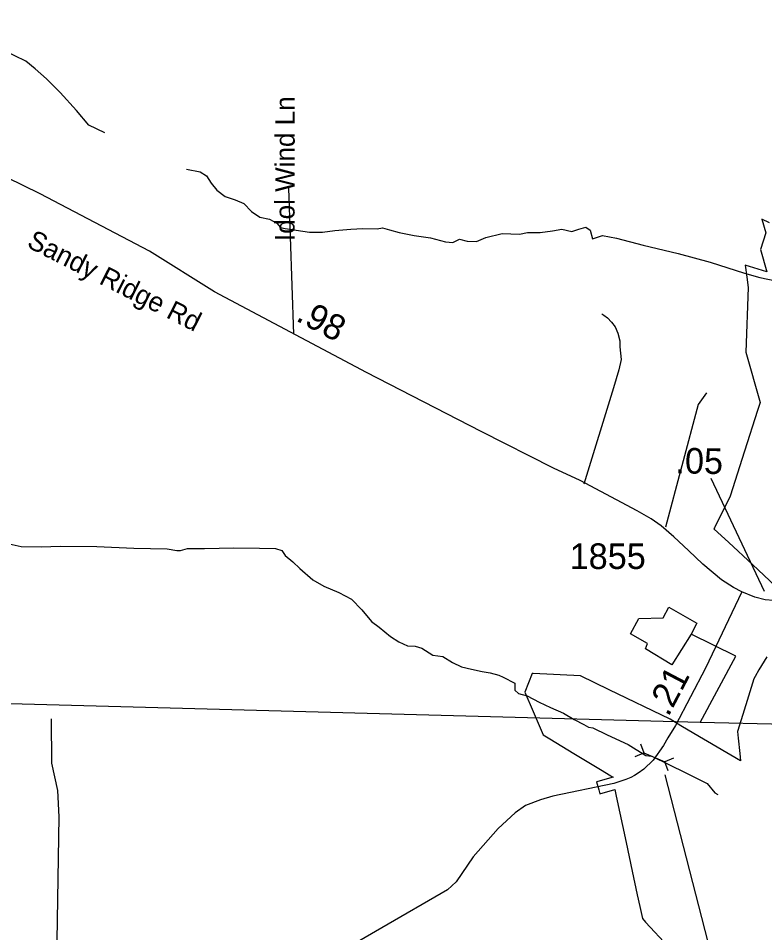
# Model space of a CAD drawing. Extents: x 1662474 to 1856135, y 779280 to 917889.
# Drawn here: x 1694127 to 1697773, y 839326 to 843789 of the extents above; entities that cross this region are included whole.
import ezdxf

# ---------------------------------------------------------------- set-up
doc = ezdxf.new("R2010")
doc.units = 0
for name, color, linetype in [('Exist Boundary Political City Limit New', 7, 'Continuous'), ('Exist Hydrographic Creek Single Shore', 7, 'Continuous'), ('Exist Road Non-System Type 51', 7, 'Continuous'), ('Exist Road Non-System Type 51 Label', 7, 'Continuous'), ('Exist Road Secondary Mileage Hundredths English Label', 7, 'Continuous'), ('Exist Road Secondary Mileage Tenths English Label', 7, 'Continuous'), ('Exist Road Secondary Structure Pipe CELL', 7, 'Continuous'), ('Exist Road Secondary Structure Pipe Number Label', 7, 'Continuous'), ('Exist Road Secondary Type 51 Attributed', 7, 'Continuous'), ('Exist Road Secondary Type 51 Label', 7, 'Continuous'), ('Exist Road Secondary Type 51 Number Label', 7, 'Continuous'), ('Exist Utilities Electrical Transmission Line', 7, 'Continuous'), ('Map Preparation Boundary City Limit Buffer Line', 7, 'Continuous')]:
    doc.layers.add(name, color=color, linetype=linetype)

msp = doc.modelspace()

# ---------------------------------------------------------------- linework, layer by layer
at = {"layer": 'Exist Boundary Political City Limit New'}
for points in [[(1697797.1, 842790.2), (1697759.9, 842808.9), (1697778.6, 842742.1), (1697752.8, 842661.1), (1697783.4, 842551.6), (1697677.9, 842584.1), (1697685.9, 842525.6), (1697692.6, 842475.4), (1697681.2, 842158.8), (1697750.5, 841914.4), (1697738, 841874.9), (1697674.9, 841675.7), (1697605.2, 841456.2), (1697527.9, 841302.1), (1697525.2, 841296.9), (1697597.6, 841229.8), (1697712.9, 841122.9), (1697826.6, 841017.4)], [(1697783.6, 840673.1), (1697745.4, 840608.4), (1697727.1, 840576.4), (1697720.4, 840564.9), (1697694.4, 840480.8), (1697666.4, 840390.5), (1697640.9, 840308.2), (1697644, 840275.1), (1697651.2, 840200.8), (1697654.8, 840164.2), (1697426.5, 840298.2), (1697363.4, 840335.2), (1697311.6, 840367.6), (1697014, 840512), (1696873.1, 840580.4), (1696641.9, 840591.4), (1696637.6, 840591.6), (1696601.8, 840499.2), (1696642.1, 840405.1), (1696690.5, 840292.2), (1696723.8, 840272.1), (1696840.6, 840201.3), (1696913.4, 840157.2), (1696971.1, 840122.3), (1697020.9, 840092.2), (1697027, 840088.4), (1697032.5, 840085.1)], [(1697032.5, 840085.1), (1696981.5, 840070.5), (1696954, 840062.6), (1696951, 840061.8), (1696962.5, 840023.4), (1696968.5, 840003.2), (1697041.1, 840024.7), (1697047, 839992.9), (1697095.8, 839766.4), (1697126, 839626.1), (1697150.8, 839510.9), (1697163, 839453.9), (1697175.9, 839394.4), (1697191, 839377.4), (1697303.5, 839257.3)]]:
    msp.add_lwpolyline(points, dxfattribs=at)
at = {"layer": 'Exist Hydrographic Creek Single Shore'}
for points in [[(1694549.1, 843229.5), (1694470.9, 843267.1), (1694411.2, 843340), (1694330.8, 843427.1), (1694265.1, 843494.1), (1694209.8, 843543.4), (1694164.4, 843580.4), (1694056.8, 843631.9), (1694004.8, 843658.1), (1693935, 843671.2), (1693848.6, 843674.6), (1693766.5, 843694.1), (1693662, 843700.4), (1693561.2, 843692.8), (1693510.2, 843680.9), (1693485.6, 843702.4), (1693391.4, 843789.3)], [(1694948.8, 843053.4), (1695015.8, 843040.3), (1695047, 843021.1), (1695069, 842984.7), (1695096.2, 842950.6), (1695137.5, 842919.1), (1695185.8, 842902.5), (1695229.4, 842884.7), (1695266.6, 842845.8), (1695307, 842818.2), (1695353.8, 842809.4), (1695390, 842789.9), (1695407.5, 842767.9), (1695429.9, 842763.4), (1695549.2, 842745.6), (1695613.4, 842745.1), (1695672.6, 842753.9), (1695732, 842758.2), (1695750.9, 842760.2), (1695809.6, 842763.1), (1695880.5, 842761.8), (1695906.2, 842767.1), (1695940.4, 842757.1), (1695987, 842742.9), (1696061.6, 842729.1), (1696141.4, 842718.2), (1696214.4, 842698.1), (1696249.5, 842695.4), (1696282.9, 842711.2), (1696319, 842701.8), (1696365.2, 842699.1), (1696411.4, 842718.6), (1696491, 842738.8), (1696574.9, 842735.6), (1696613.8, 842744.5), (1696676.2, 842744), (1696736.6, 842752.4), (1696783, 842760.5), (1696831.6, 842749.2), (1696865.5, 842759.2), (1696898.8, 842769.2), (1696920.6, 842754.8), (1696932.1, 842712.8), (1696981, 842729.1), (1697048.9, 842716.4), (1697179.6, 842681.8), (1697350.2, 842640.9), (1697506.9, 842598.1), (1697674.6, 842545.3), (1697749.9, 842523.8), (1697835.2, 842506.2)], [(1694053.2, 841229.9), (1694141.2, 841211), (1694238.1, 841208.7), (1694332.5, 841212.1), (1694511, 841210.8), (1694691.4, 841202.1), (1694854.6, 841199.8), (1694901.2, 841191.6), (1694920.1, 841191.1), (1694954, 841201.6), (1695000, 841201.1), (1695037.2, 841200.5), (1695179.5, 841204.8), (1695305.8, 841202.4), (1695383.6, 841200.8), (1695414.4, 841191.6), (1695430.9, 841166.4), (1695468.8, 841135.4), (1695501.8, 841104.2), (1695565.9, 841048.3), (1695619.9, 841016.6), (1695692.4, 840985.8), (1695755, 840954.1), (1695805.8, 840901.1), (1695851.9, 840845.7), (1695890, 840817.9), (1695944.8, 840771.9), (1695986.5, 840745.2), (1696027.8, 840726.8), (1696066, 840724.7), (1696099.1, 840714.2), (1696152.1, 840680.4), (1696201.2, 840673.5), (1696247.4, 840644.1), (1696292.2, 840623.4), (1696341.6, 840612.1), (1696392.5, 840600.6), (1696432.1, 840593.8), (1696474.1, 840582.7), (1696496, 840572.8), (1696552.4, 840543.9), (1696552.9, 840510.2), (1696570, 840492.7), (1696613.2, 840482.2), (1696671.5, 840450.9), (1696726.4, 840425.2), (1696790.6, 840397.4), (1696842.9, 840367.2), (1696889.4, 840342.1), (1696912.8, 840329.4), (1696933.8, 840326.1), (1697003.2, 840291.9), (1697107.1, 840244.4), (1697193.2, 840190.1), (1697222.4, 840187.2), (1697388, 840106.9), (1697492.2, 840054.4), (1697529.2, 840009), (1697543.9, 840000.1)]]:
    msp.add_lwpolyline(points, dxfattribs=at)
at = {"layer": 'Exist Road Non-System Type 51'}
msp.add_line((1695472.8, 842247.4), (1695447.9, 842959.8), dxfattribs=at)
for points in [[(1696976.9, 842346.7), (1696986.9, 842340.9), (1697005, 842327.2), (1697025.2, 842306.8), (1697042.6, 842283.1), (1697056.1, 842252.4), (1697066.1, 842215.7), (1697066.4, 842185.5), (1697072.5, 842123.9), (1697059.9, 842072.9), (1697034.1, 841984.7), (1696889.8, 841515.7)], [(1697488.5, 841961.9), (1697448.9, 841903.6), (1697288.5, 841305.8)], [(1694288.2, 840370.4), (1694289.9, 840153.8), (1694317.9, 840019.2), (1694325.2, 839891.4), (1694315.6, 839288.2), (1694329.8, 838810.2), (1694332.1, 838562.8), (1694336.6, 838412.4)]]:
    msp.add_lwpolyline(points, dxfattribs=at)
at = {"layer": 'Exist Road Secondary Mileage Tenths English Label'}
msp.add_line((1697772.9, 840991.5), (1697511.4, 841543.1), dxfattribs=at)
at = {"layer": 'Exist Road Secondary Structure Pipe CELL'}
for p, q in [((1697139.9, 840185.7), (1697183, 840204.2)), ((1697166.9, 840248.2), (1697183, 840204.2)), ((1697183, 840204.2), (1697285.5, 840160)), ((1697328.5, 840178.5), (1697285.5, 840160)), ((1697301.6, 840116), (1697285.5, 840160))]:
    msp.add_line(p, q, dxfattribs=at)
at = {"layer": 'Exist Road Secondary Structure Pipe Number Label'}
msp.add_line((1697285.7, 840096.9), (1697814.5, 838042.6), dxfattribs=at)
at = {"layer": 'Exist Road Secondary Type 51 Attributed'}
for points in [[(1697662, 840989.5), (1697620.8, 841010.1), (1697562.4, 841049), (1697470.8, 841124.6), (1697401, 841192.1), (1697328.9, 841258.5), (1697267, 841312.3), (1697219, 841346.7), (1697150.3, 841384.5), (1696872.1, 841532.5), (1696741.6, 841592.8), (1696388.9, 841772.6), (1695827.4, 842059.9), (1695085.5, 842454.9), (1694767.3, 842653), (1694233.2, 842932.3), (1693740.9, 843172.7), (1693379.1, 843374.2), (1693151.3, 843525.3)], [(1697662, 840989.5), (1697484.5, 840617.2), (1697337.7, 840337.8), (1697300.5, 840277.5), (1697279, 840239.8), (1697227.7, 840167.4), (1697183.3, 840124.9), (1697155.9, 840105), (1697138, 840092.7), (1697119.1, 840083.3), (1697095.5, 840072.9)], [(1697991.4, 840957.4), (1697962.5, 840954), (1697899, 840944.8), (1697816.3, 840947.1), (1697775.4, 840950.6), (1697725.3, 840964.3), (1697662, 840989.5)], [(1697095.5, 840072.9), (1697036, 840054), (1696738.7, 839992.6), (1696678.3, 839975.1), (1696604.6, 839946.8), (1696553.7, 839910.9), (1696470.6, 839835.3), (1696349.2, 839696.9), (1696265.3, 839573.7), (1696223.4, 839534.4), (1695903.5, 839348.9), (1695192.9, 838937.5), (1694576, 838564.2), (1694339.4, 838423.4), (1694221.1, 838325.9), (1694099.1, 838209.5), (1693911.4, 838007.3)]]:
    msp.add_lwpolyline(points, dxfattribs=at)
at = {"layer": 'Exist Utilities Electrical Transmission Line'}
for p, q in [((1697457.4, 840352.2), (1692050.9, 840498.4)), ((1704475.7, 840197.4), (1697457.4, 840352.2))]:
    msp.add_line(p, q, dxfattribs=at)
for points in [[(1697414, 840782.9), (1697320.4, 840633.7), (1697191.1, 840711.2), (1697201.4, 840737.2), (1697117.9, 840784.1), (1697158.8, 840859.7), (1697276.8, 840862.3), (1697305.4, 840914.2), (1697442.5, 840836.6), (1697414, 840782.9)], [(1697457.4, 840352.2), (1697632.8, 840676.4), (1697414, 840782.9)]]:
    msp.add_lwpolyline(points, dxfattribs=at)
at = {"layer": 'Map Preparation Boundary City Limit Buffer Line'}
for points in [[(1697797.1, 842790.2), (1697759.9, 842808.9), (1697778.6, 842742.1), (1697752.8, 842661.1), (1697783.4, 842551.6), (1697677.9, 842584.1), (1697685.9, 842525.6), (1697692.6, 842475.4), (1697681.2, 842158.8), (1697750.5, 841914.4), (1697738, 841874.9), (1697674.9, 841675.7), (1697605.2, 841456.2), (1697527.9, 841302.1), (1697525.2, 841296.9), (1697597.6, 841229.8), (1697712.9, 841122.9), (1697826.6, 841017.4)], [(1697783.6, 840673.1), (1697745.4, 840608.4), (1697727.1, 840576.4), (1697720.4, 840564.9), (1697694.4, 840480.8), (1697666.4, 840390.5), (1697640.9, 840308.2), (1697644, 840275.1), (1697651.2, 840200.8), (1697654.8, 840164.2), (1697426.5, 840298.2), (1697363.4, 840335.2), (1697311.6, 840367.6), (1697014, 840512), (1696873.1, 840580.4), (1696641.9, 840591.4), (1696637.6, 840591.6), (1696601.8, 840499.2), (1696642.1, 840405.1), (1696690.5, 840292.2), (1696723.8, 840272.1), (1696840.6, 840201.3), (1696913.4, 840157.2), (1696971.1, 840122.3), (1697020.9, 840092.2), (1697027, 840088.4), (1697032.5, 840085.1)], [(1697032.5, 840085.1), (1696981.5, 840070.5), (1696954, 840062.6), (1696951, 840061.8), (1696962.5, 840023.4), (1696968.5, 840003.2), (1697041.1, 840024.7), (1697047, 839992.9), (1697095.8, 839766.4), (1697126, 839626.1), (1697150.8, 839510.9), (1697163, 839453.9), (1697175.9, 839394.4), (1697191, 839377.4), (1697303.5, 839257.3)]]:
    msp.add_lwpolyline(points, dxfattribs=at)

# ---------------------------------------------------------------- texts
at = {"layer": 'Exist Road Non-System Type 51 Label'}
msp.add_text('Idol Wind Ln', height=95, rotation=89.9111, dxfattribs=at).set_placement((1695476.5, 842701.8))
at = {"layer": 'Exist Road Secondary Mileage Hundredths English Label'}
msp.add_text('.98', height=125, rotation=331.9688, dxfattribs=at).set_placement((1695477.8, 842316.2))
at = {"layer": 'Exist Road Secondary Mileage Tenths English Label'}
for s, rotation, p in [('.05', 359.0671, (1697336.5, 841568.2)), ('.21', 62.2804, (1697302.2, 840376))]:
    msp.add_text(s, height=125, rotation=rotation, dxfattribs=at).set_placement(p)
at = {"layer": 'Exist Road Secondary Type 51 Label'}
msp.add_text('Sandy Ridge Rd', height=95, rotation=333.1498, dxfattribs=at).set_placement((1694163.8, 842675.3))
at = {"layer": 'Exist Road Secondary Type 51 Number Label'}
msp.add_text('1855', height=125, dxfattribs=at).set_placement((1696820.4, 841101.2))

doc.saveas('drawing.dxf')
